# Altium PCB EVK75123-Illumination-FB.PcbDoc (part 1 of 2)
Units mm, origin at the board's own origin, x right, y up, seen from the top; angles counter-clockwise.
Board outline 80 x 50 mm, 4 copper layers (Top Layer, GND, VCC, Bottom Layer), stack 0.99 mm thick; 109 components, 50 nets, 287 pads, 1161 vias.
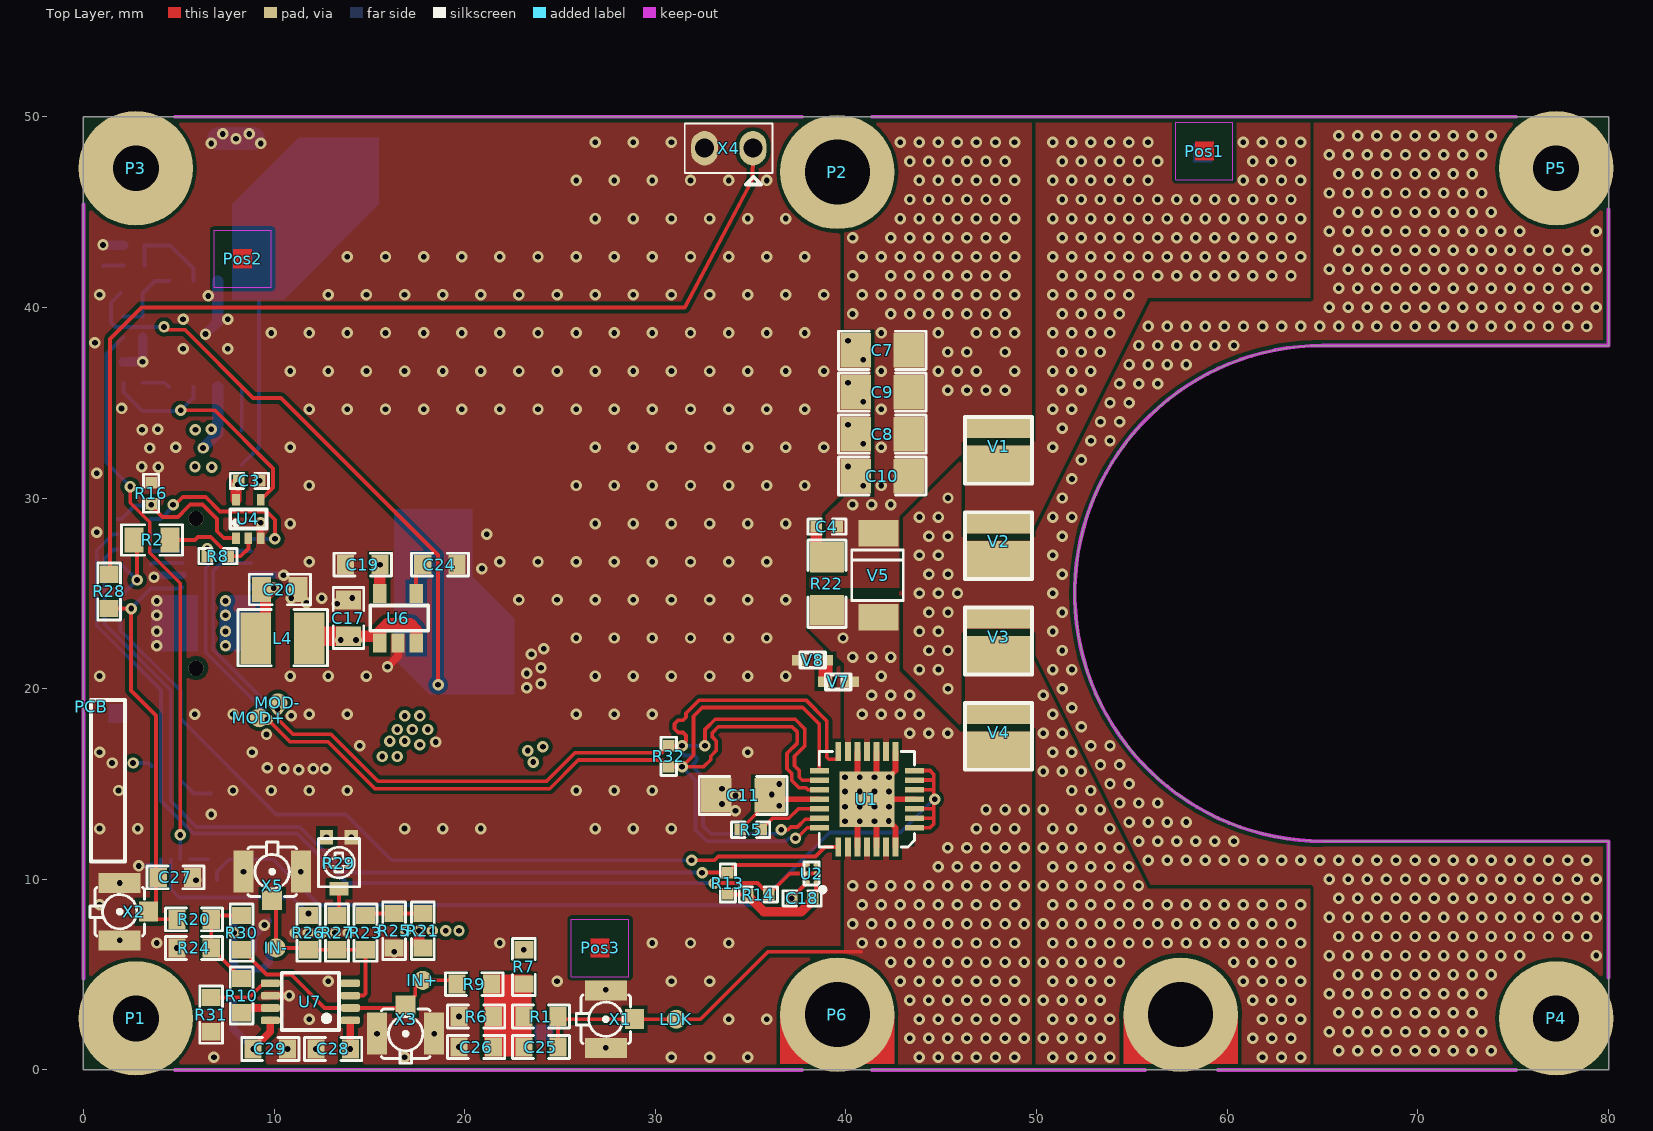
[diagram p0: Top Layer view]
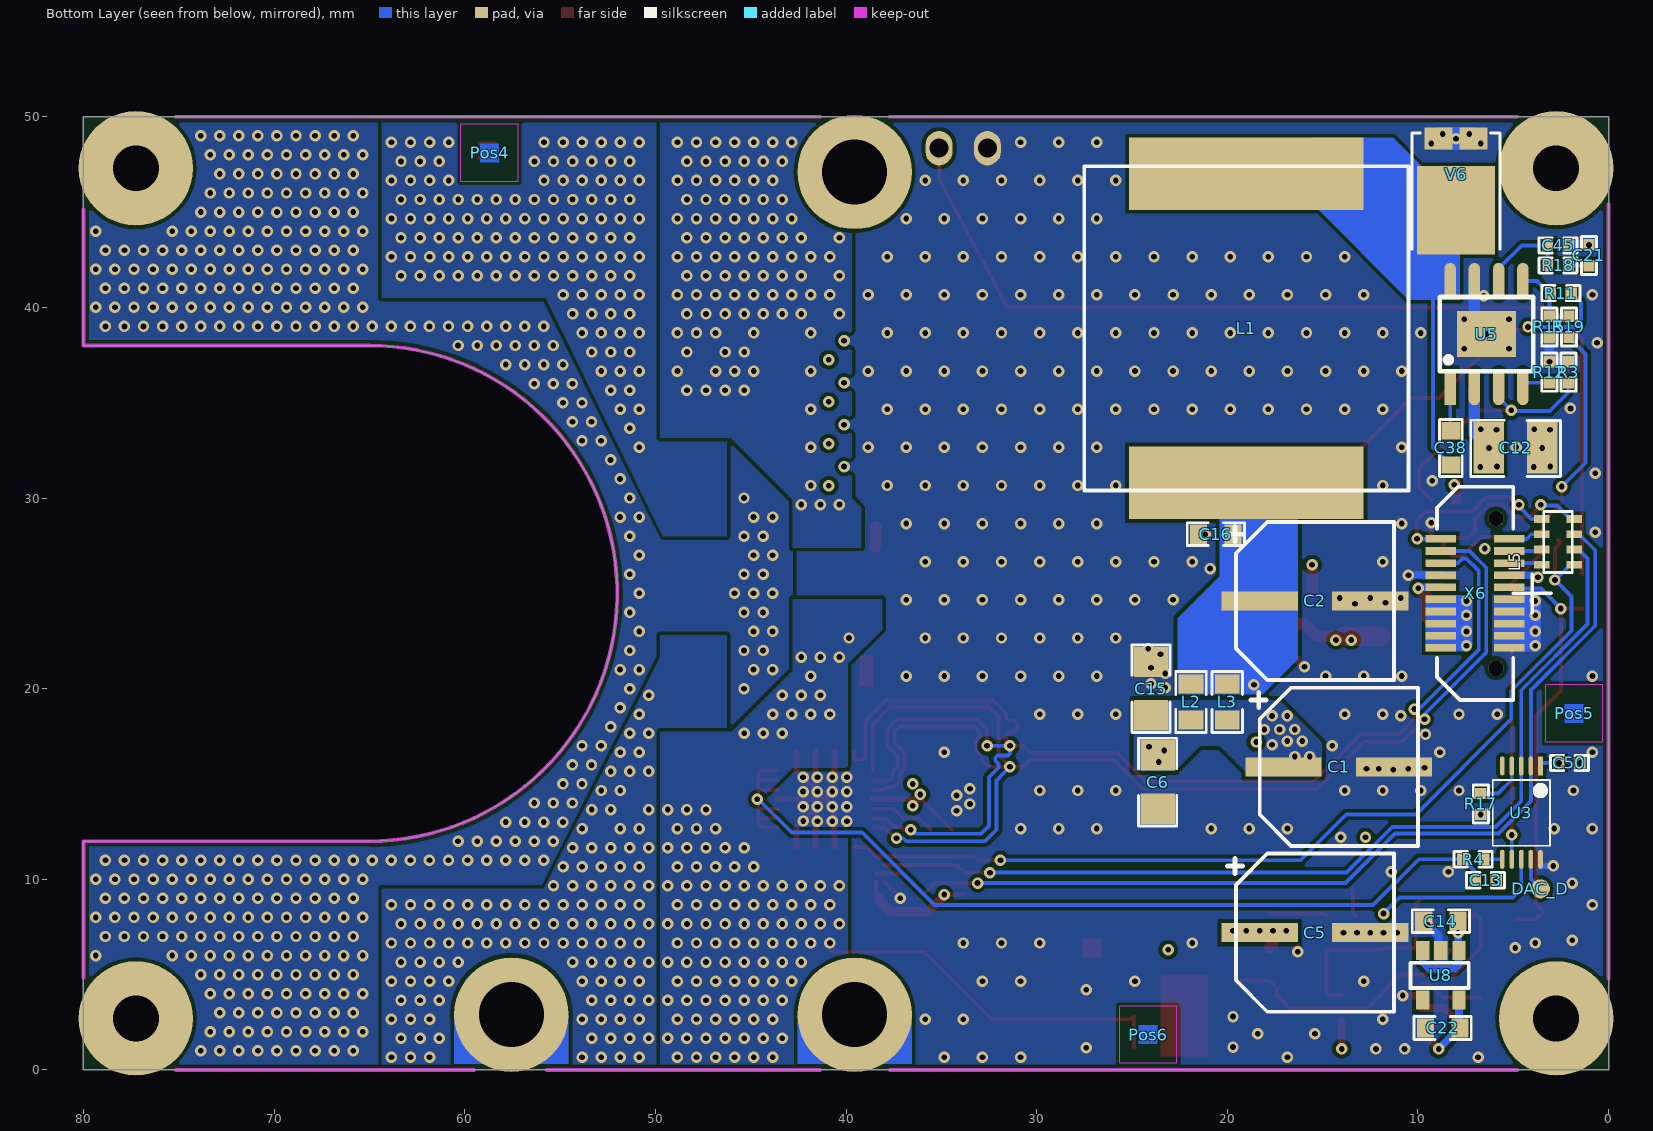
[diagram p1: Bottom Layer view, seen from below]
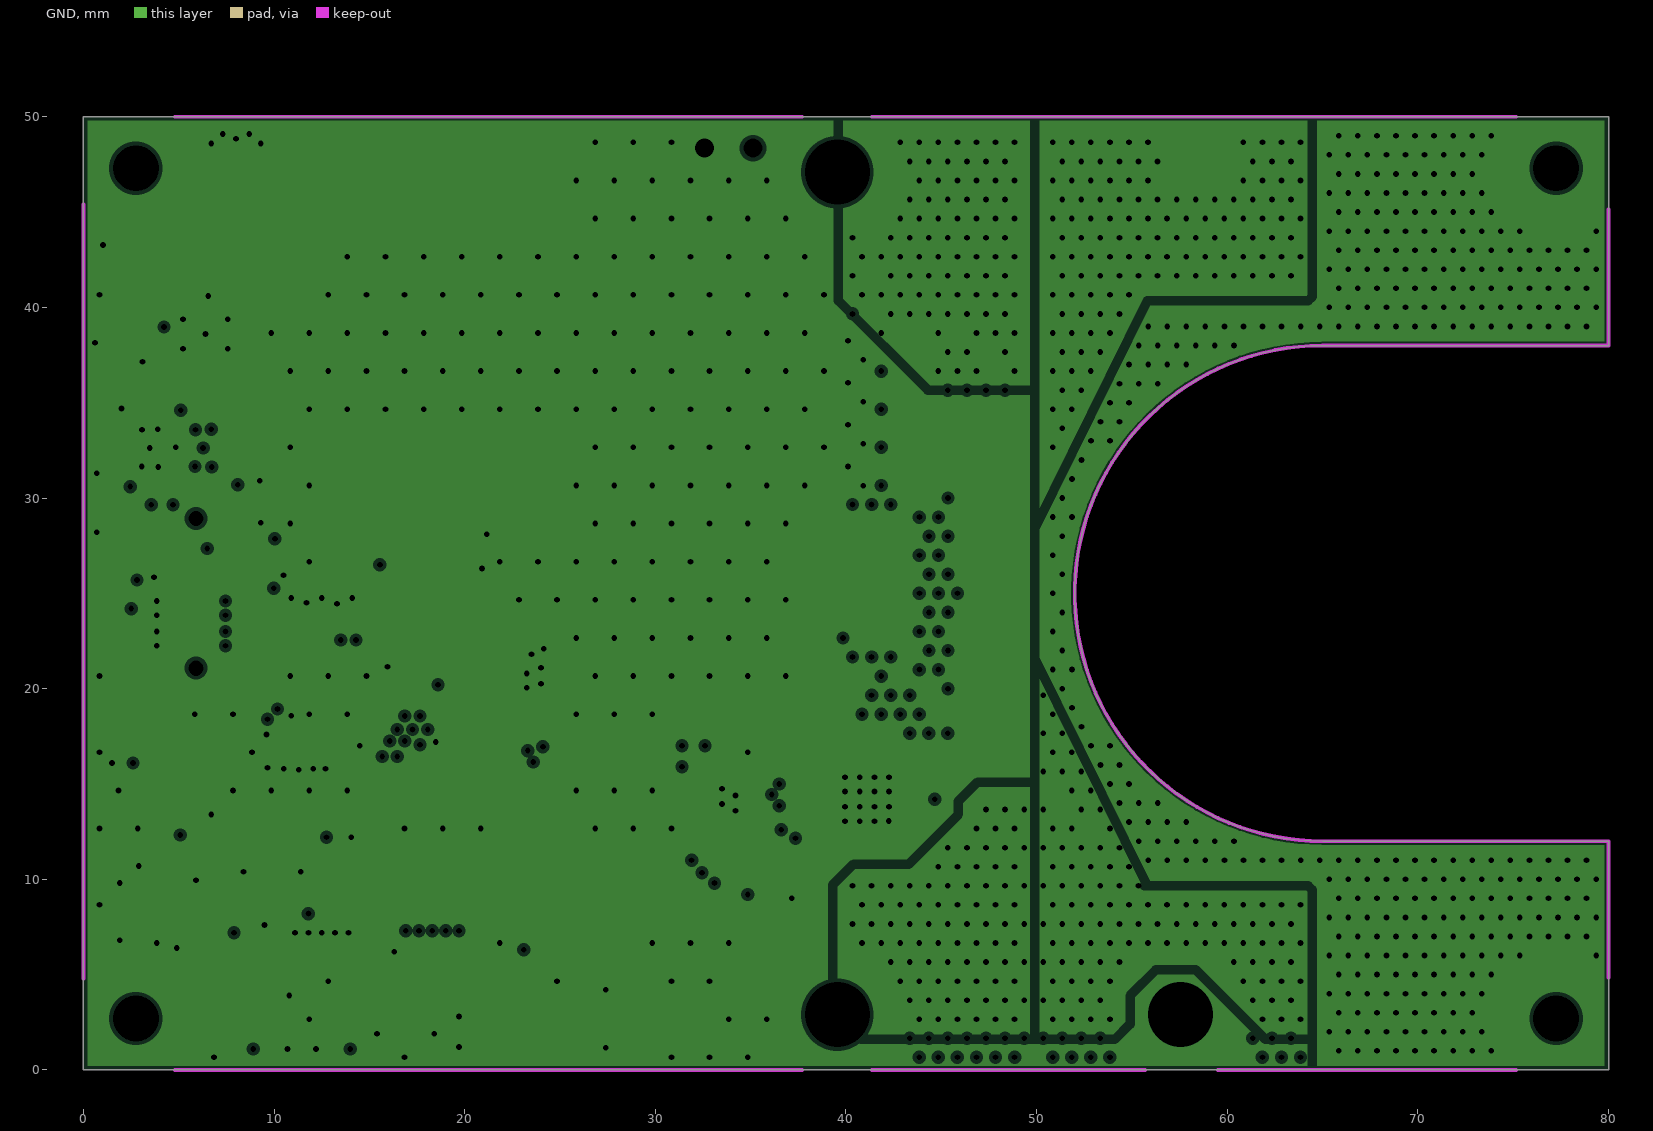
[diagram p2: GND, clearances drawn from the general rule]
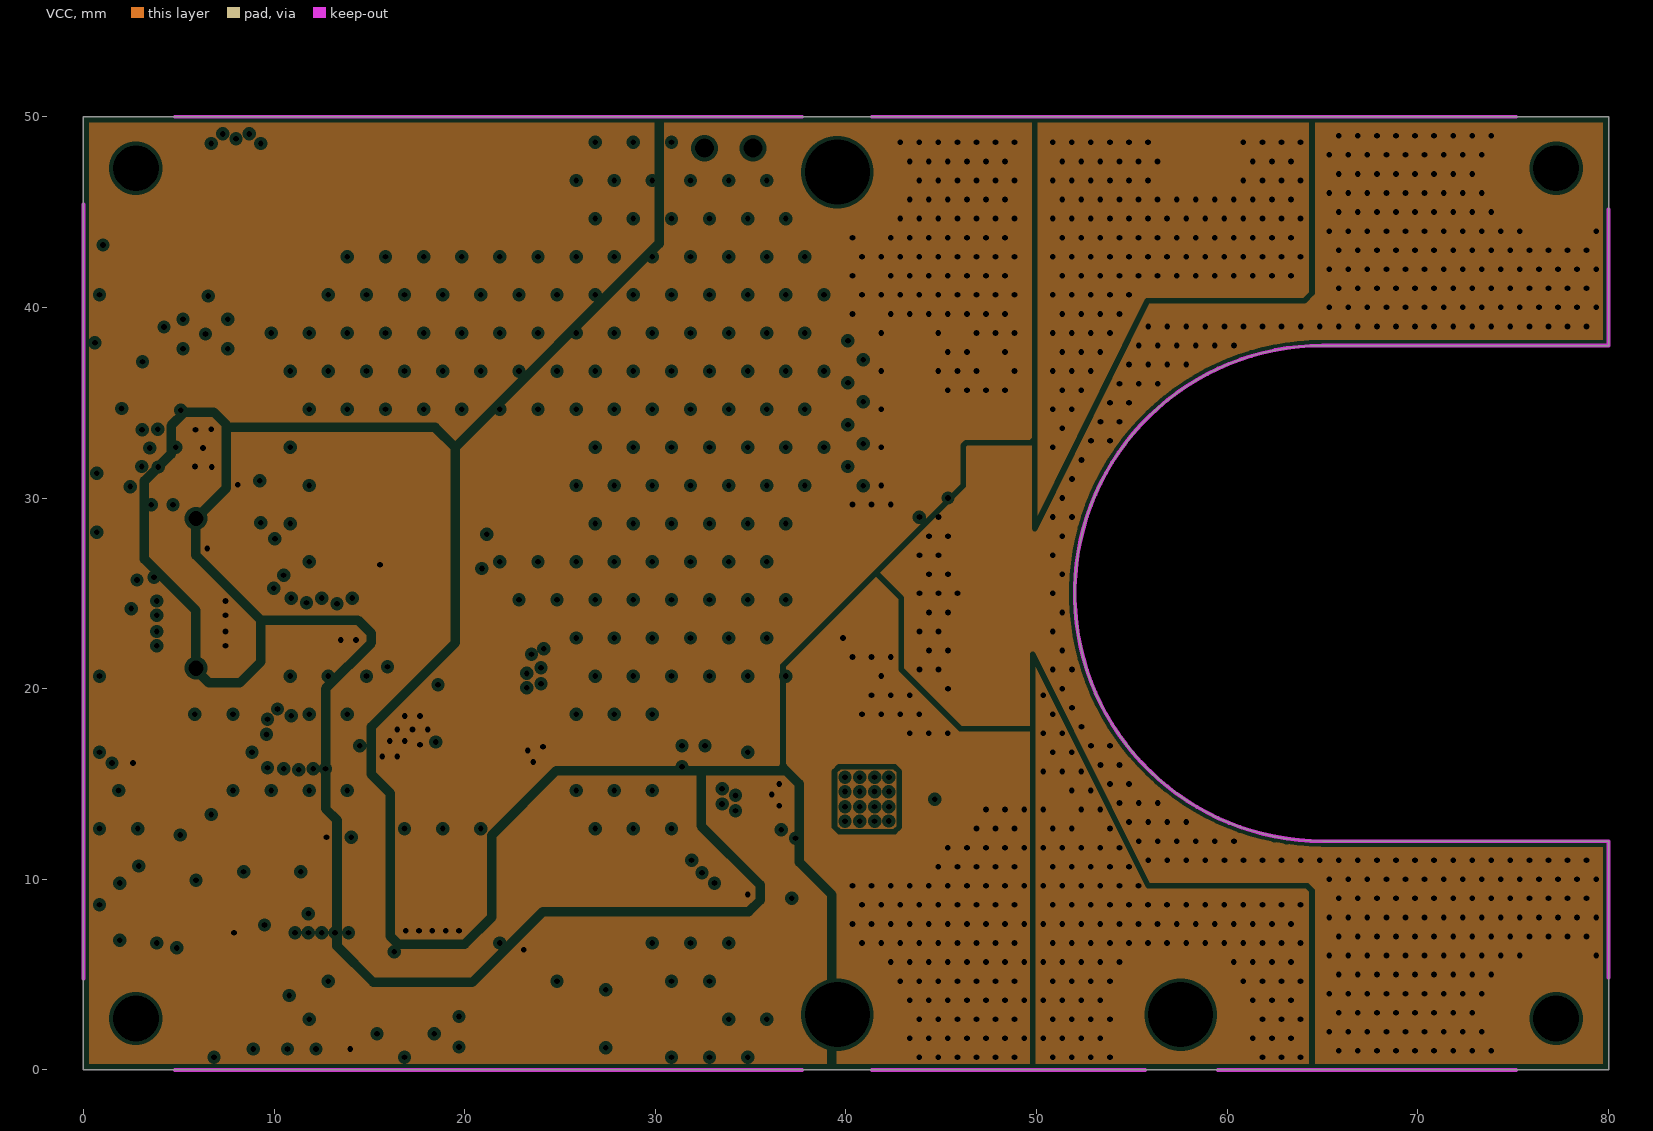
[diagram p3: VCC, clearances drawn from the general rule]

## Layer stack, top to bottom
Top Solder: solder mask 0.025, Solder Resist, Dk 3.5
Top Layer: signal copper 0.07
Dielectric1: prepreg 0.15, FR-4, Dk 4.3
GND: plane copper 0.07, net (Multiple Nets)
Dielectric3: core 0.41, FR-4, Dk 4.47
VCC: plane copper 0.07, net (Multiple Nets)
Dielectric2: prepreg 0.15, FR-4, Dk 4.3
Bottom Layer: signal copper 0.07
Bottom Solder: solder mask 0.025, Solder Resist, Dk 3.5

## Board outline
0,0 0,50 80,50 80,38 65,38 ccw(c65,25) 65,12 80,12 80,0

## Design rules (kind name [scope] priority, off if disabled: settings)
AssemblyTestPointUsage [not (NetPinCount = 1)] p1: allowmultiple=TRUE
AssemblyTestpoint AssemblyTestpoint_Pad [(IsPad And (OnTopLayer)OR (OnBottom))] p1: testpointundercomponent=TRUE minsize=0.8 maxsize=3 preferedsize=0.8 minholesize=0 maxholesize=0 preferedholesize=0 testpointgrid=0.025 usegrid=FALSE gridtolerance=0 allowsidebottom=TRUE minspacing=2.54
AssemblyTestpoint AssemblyTestpoint_Via [(IsVia)] p2: testpointundercomponent=TRUE minsize=0.6 maxsize=0.8 preferedsize=0.8 minholesize=0 maxholesize=0.3 preferedholesize=0.3 testpointgrid=0.025 usegrid=FALSE gridtolerance=0 allowsidebottom=TRUE minspacing=2.54
AssemblyTestpoint AssemblyTestpoint_THT [(IsPad And OnMultiLayer)] p3: testpointundercomponent=TRUE minsize=0.5 maxsize=5 preferedsize=1.524 minholesize=0 maxholesize=3 preferedholesize=0.813 testpointgrid=0.025 usegrid=FALSE gridtolerance=0 allowsidetop=TRUE allowsidebottom=TRUE
AssemblyTestpoint [All] p4: testpointundercomponent=TRUE minsize=1.016 maxsize=2.54 preferedsize=1.524 minholesize=0 maxholesize=1.016 preferedholesize=0.813 testpointgrid=0.025 usegrid=TRUE gridtolerance=0 allowsidetop=TRUE allowsidebottom=TRUE
Clearance Clearance_Hole [All vs not PadIsPlated] p1: gap=0.23 ignorepadtopadclearanceinfootprint=FALSE except(0: Arc-Hole Track-Hole SMDPad-Hole THPad-Hole Via-Hole Fill-Hole Poly-Hole Region-Hole Text-Hole)
Clearance Clearance_poly [inpolygon] p2: gap=0.2 ignorepadtopadclearanceinfootprint=FALSE except(0: Arc-Hole Track-Hole SMDPad-Hole THPad-Hole Via-Hole Fill-Hole Poly-Hole Region-Hole Text-Hole)
Clearance [All] p3: gap=0.15 ignorepadtopadclearanceinfootprint=FALSE
ComponentClearance [not HasFootprint('PAD_1mm_SMD')] p1: gap=0.1 collisioncheckmode=3 verticalgap=0.1 showdistances=FALSE
DiffPairsRouting [InDifferentialPair('MOD')] p1: maxlimit=0.2 minlimit=0.2 mostfreqgap=0.2 toplayer_minwidth=0.192 toplayer_maxwidth=0.192 toplayer_prefwidth=0.192 bottomlayer_minwidth=0.192 bottomlayer_maxwidth=0.192 bottomlayer_prefwidth=0.192 maxuncoupledlength=17
HoleSize [All] p1: absolutevalues=TRUE maxlimit=3.5 minlimit=0.3 maxpercent=80.000 minpercent=20.000
MatchedLengths MOD [InxSignalClass('MOD')] p1: tolerance=0.2 checknetsindiffpair=FALSE checkdiffpairvsdiffpair=TRUE checkxsignals=TRUE checkothers=TRUE
MatchedLengths MOD_DC [InxSignalClass('All xSignals')] p2: tolerance=0.2 checknetsindiffpair=TRUE checkdiffpairvsdiffpair=FALSE checkxsignals=FALSE checkothers=FALSE
MinimumSolderMaskSliver [All vs IsVia] p1: minsoldermaskwidth=0.1
PlaneClearance PlaneClearance_MH [InPadClass('MH')] p1: clearance=0.5
PlaneClearance [All] p2: clearance=0.2
PlaneConnect [All] p1: planeconnectstyle=Direct reliefexpansion=0.5 reliefentries=4 reliefconductorwidth=0.3 reliefairgap=0.2
PolygonConnect [All] p1: connectstyle=Direct reliefconductorwidth=0.3 reliefentries=4 polygonreliefangle="90 Angle" airgapwidth=0.254
RoutingVias [All] p1: holewidth=0.3 width=0.6 viastyle="Through Hole" minholewidth=0.3 minwidth=0.6 maxholewidth=0.3 maxwidth=0.6
SilkToSolderMaskClearance SilkscreenOverComponentPads [IsPad] p1: minsilkscreentomaskgap=0.254 clearancetoexposedcopper=TRUE
SolderMaskExpansion SolderMaskExpansion_Via [IsVia] p1: expansion=-0.05
SolderMaskExpansion SolderMaskExpansion_ALL [All] p2: expansion=0.05
UnConnectedPin [All] p1:
ViasUnderSMD [All] p1: allowed=TRUE
Width [All] p1: maxlimit=3 minlimit=0.2 preferedwidth=0.2 checkconnectedcopper=TRUE
21 further rules are at their usual default settings.

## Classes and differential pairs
pad class MH: Free-H1 P1-1 P2-1 P3-1 P4-1 P5-1 P6-1
component class U_Laserdriver: C4 C7 C8 C9 C10 C11 C13 C25 C26 C27 C28 C29 IN+ IN- LDK R1 R4 R5 R6 R7 R9 R10 R20 R21 R22 R23 R24 R25 R26 R27 R28 R29 R30 R31 R32 U1 U7 V1 V2 V3 V4 V5 V7 V8 X1 X2 X3 X4 X5
net class <HiSpeed>: CMPO LDK MOD_N MOD_P NAMS2 NAMS3 NAMS4 NAMS5 NAMS6 NAMS7 NAMS8 NAMS9 NAMS10 NetC25_2 NetIN+_1 NetR10_1
net class <Power>: 1V8 3V3 5V0 17V 24V GND VLD
component class EVK75123-Illumination-FB: C3 C17 C18 C20 C50 DAC_D L4 L5 MOD+ MOD- PCB R2 R8 R13 R14 R16 R17 U2 U3 U4 X6
net class DIFF100: MOD_N MOD_P
component class U_Power: 24V C1 C2 C5 C6 C12 C14 C15 C16 C19 C21 C22 C24 C38 C45 L1 L2 L3 P1 P2 P3 P4 P5 P6 Pos1 Pos2 Pos3 Pos4 Pos5 Pos6 R3 R11 R12 R15 R18 R19 U5 U6 U8 V6
differential pair MOD: +MOD_P -MOD_N

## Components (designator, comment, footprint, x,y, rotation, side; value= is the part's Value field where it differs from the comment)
C1 "Polarized Capicator" ELKO_SMD-8x7 14.15,15.9 r0 bottom
C2 "Polarized Capicator" ELKO_SMD-8x7 15.4,24.6 r0 bottom
C3 "Capacitor non-polarized" 0402 8.7,30.9 r0 top
C4 "Capacitor non-polarized" 0402 39,28.5 r0 top
C5 "Polarized Capicator" ELKO_SMD-8x7 15.4,7.2 r0 bottom
C6 "Capacitor non-polarized" 1206 23.65,15.1 r270 bottom
C7 "Capacitor non-polarized" 1206 41.9,37.75 r0 top
C8 "Capacitor non-polarized" 1206 41.9,33.35 r0 top
C9 "Capacitor non-polarized" 1206 41.9,35.55 r0 top
C10 "Capacitor non-polarized" 1206 41.9,31.15 r0 top
C11 "Capacitor non-polarized" 1206 34.6,14.4 r0 top
C12 "Capacitor non-polarized" 1210 4.875,32.625 r0 bottom
C13 "Capacitor non-polarized" 0402 6.45,9.95 r0 bottom
C14 "Capacitor non-polarized" 0603 8.793,7.8 r180 bottom
C15 "Capacitor non-polarized" 1206 24,20 r270 bottom
C16 "Capacitor non-polarized" 0603 20.6,28.1 r0 bottom
C17 "Capacitor non-polarized" 0805 13.9,23.7 r270 top
C18 "Capacitor non-polarized" 0402 37.7,9 r0 top
C19 "Capacitor non-polarized" 0603 14.65,26.5 r0 top
C20 "Capacitor non-polarized" 0805 10.3,25.2 r180 top
C21 "Capacitor non-polarized" 0402 1.025,42.725 r270 bottom
C22 "Capacitor non-polarized" 0603 8.7,2.2 r180 bottom
C24 "Capacitor non-polarized" 0603 18.7,26.5 r0 top
C25 "Capacitor non-polarized" 0603 24,1.2 r180 top
C26 "Capacitor non-polarized" 0603 20.6,1.2 r180 top
C27 "Capacitor non-polarized" 0603 4.825,10.1 r0 top
C28 "Capacitor non-polarized" 0603 13.1,1.1 r180 top
C29 "Capacitor non-polarized" 0603 9.8,1.1 r0 top
C38 "Capacitor non-polarized" 0603 8.275,32.625 r90 bottom
C45 "Capacitor non-polarized" 0402 2.65,43.25 r0 bottom
C50 "Capacitor non-polarized" 0402 2.05,16.1 r0 bottom
DAC_D "Test Pad" PAD_1mm_SMD 3.575,9.5 r180 bottom
IN+ "Test Pad" PAD_1mm_SMD 17.8,4.7 r0 top
IN- "Test Pad" PAD_1mm_SMD 10.1,6.4 r0 top
L1 "Inductor" VIS-IHLP-6767DZ 19,38.9 r270 bottom
L2 "Ferrite" 0805 21.9,19.3 r270 bottom
L3 "Ferrite" 0805 20,19.3 r270 bottom
L4 "Inductor" 1210 10.45,22.65 r0 top
L5 "Ferrite" 1206_FB-array 2.65,27.7 r90 bottom
LDK "Test Pad" PAD_1mm_SMD 31.1,2.659 r0 top
MOD+ "Test Pad" PAD_1mm_SMD 9.225,18.475 r0 top
MOD- "Test Pad" PAD_1mm_SMD 10.2,19.25 r0 top
P1 "Test Pad" PAD_M2-5x5#1 2.75,2.7 r270 top
P2 "Test Pad" PAD_M2-5x5#2 39.55,47.1 r270 top
P3 "Test Pad" PAD_M2-5x5#1 2.75,47.3 r270 top
P4 "Test Pad" PAD_M2-5x5#1 77.25,2.7 r270 top
P5 "Test Pad" PAD_M2-5x5#1 77.25,47.3 r270 top
P6 "Test Pad" PAD_M2-5x5#2 39.55,2.9 r90 top
PCB "850-5390" PCB 0.725,19.05 r270 top
Pos1 "Position" Pos-QUADRAT 58.8,48.2 r0 top
Pos2 "Position" Pos-QUADRAT 8.35,42.55 r0 top
Pos3 "Position" Pos-QUADRAT 27.1,6.4 r0 top
Pos4 "Position" Pos-QUADRAT 58.7,48.1 r180 bottom
Pos5 "Position" Pos-QUADRAT 1.8,18.7 r180 bottom
Pos6 "Position" Pos-QUADRAT 24.15,1.85 r180 bottom
R1 "Resistor" 0603 24,2.8 r180 top
R2 "Resistor" 0805 3.6,27.8 r0 top
R3 "Resistor" 0402 2.1,36.6 r270 bottom
R4 "Resistor" 0402 7.1,11.05 r180 bottom
R5 "Resistor" 0402 35,12.6 r180 top
R6 "Resistor" 0603 20.6,2.8 r180 top
R7 "Resistor" 0603 23.1,5.4 r270 top
R8 "Resistor" 0402 7.05,26.95 r180 top
R9 "Resistor" 0603 20.5,4.5 r180 top
R10 "Resistor" 0603 8.3,3.9 r90 top
R11 "Resistor" 0402 2.5,40.75 r0 bottom
R12 "Resistor" 0402 3.1,36.6 r90 bottom
R13 "Resistor" 0402 33.8,9.8 r270 top
R14 "Resistor" 0402 35.4,9.2 r180 top
R15 "Resistor" 0402 3.1,38.975 r90 bottom
R16 "Resistor" 0402 3.55,30.25 r90 top
R17 "Resistor" 0402 6.7,13.95 r90 bottom
R18 "Resistor" 0402 2.65,42.2 r180 bottom
R19 "Resistor" 0402 2.075,38.975 r270 bottom
R20 "Resistor" 0603 5.8,7.9 r180 top
R21 "Resistor" 0603 17.8,7.3 r90 top
R22 "Resistor" 1206 39,25.5 r90 top
R23 "Resistor" 0603 14.8,7.2 r270 top
R24 "Resistor" 0603 5.8,6.4 r180 top
R25 "Resistor" 0603 16.3,7.3 r270 top
R26 "Resistor" 0603 11.8,7.2 r270 top
R27 "Resistor" 0603 13.3,7.2 r270 top
R28 "Resistor" 0603 1.35,25.1 r270 top
R29 "Trimmer" POZ2AN 13.4,10.878 r180 top
R30 "Resistor" 0603 8.3,7.2 r90 top
R31 "Resistor" 0603 6.7,2.9 r90 top
R32 "Resistor" 0402 30.7,16.45 r270 top
U1 "iC-HG" QFN28-0.5-5-0.9 41.1,14.2 r180 top
U2 "TMP108" BGA6-0.4-0.25-1.2x0.8 38.2,10.3 r180 top
U3 "MCP4728" MSOP10-0.5-5 4.575,13.5 r270 bottom
U4 "Single-Gate Dual-Input AND-Logic-Gate" SOT353-0.65--2.6 8.65,28.9 r90 top
U5 "TPS54061" PSO8-1.27-7.3 6.4,38.6 r90 bottom
U6 "LP2985" SOT23-5-0.95--3.6 16.5,23.7 r90 top
U7 "LTC6752HMS8-2" TSSOP8-0.65--5 11.9,3.575 r180 top
U8 "High-Speed LDO Voltage-Regulator" SOT23-5-0.95--3.6 8.793,4.958 r270 bottom
V1 "Light Emitting Diode" PCW-SMT-2 48,32.5 r0 top
V2 "Light Emitting Diode" PCW-SMT-2 48,27.5 r0 top
V3 "Light Emitting Diode" PCW-SMT-2 48,22.5 r0 top
V4 "Light Emitting Diode" PCW-SMT-2 48,17.5 r0 top
V5 "Schottky Diode" SOD128 41.7,26.5 r270 top
V6 "Default Diode" TO-277-3 8,46.1 r0 bottom
V7 "Z-Diode" SOD523 39.6,20.35 r180 top
V8 "Z-Diode" SOD523 38.25,21.5 r180 top
X1 "Amphenol SMA-connector right-angled" HIR-2-U.FL-U.FL-R-SMT 27.4,2.659 r0 top
X2 "Amphenol SMA-connector right-angled" HIR-2-U.FL-U.FL-R-SMT 1.9,8.3 r0 top
X3 "Amphenol SMA-connector right-angled" HIR-2-U.FL-U.FL-R-SMT 16.9,1.9 r90 top
X4 "CON2(1)" PADS-2-2.54 33.85,48.35 r180 top
X5 "Amphenol SMA-connector right-angled" HIR-2-U.FL-U.FL-R-SMT 9.9,10.4 r270 top
X6 "CON20(1-2)" SAM-LSS-110-02-F-DV-A 7,25 r270 bottom locked

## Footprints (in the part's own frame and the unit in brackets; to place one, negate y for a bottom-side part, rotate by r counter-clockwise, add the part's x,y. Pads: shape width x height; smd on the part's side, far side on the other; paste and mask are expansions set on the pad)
0402 [mm]
  rect 0.6x0.6 smd: 1(-0.55,0) 2(0.55,0)
  silkscreen extent -1,-0.4 1,0.4, body extent -0.51,-0.25 0.51,0.25, height 0.41
0603 [mm]
  rect 0.9x1 smd: 1(-0.9,0) 2(0.9,0)
  silkscreen extent -1.5,-0.6 1.5,0.6, body extent -0.89,-0.38 0.89,0.38, height 0.76
0805 [mm]
  rect 1x1.3 smd: 1(-0.95,0) 2(0.95,0)
  silkscreen extent -1.6,-0.8 1.6,0.8, body extent -1,-0.51 1,0.51, height 1
1206 [mm]
  rect 1.6x1.8 smd: 1(-1.4,0) 2(1.4,0)
  silkscreen extent -2.3,-1 2.3,1, body extent -1.45,-0.76 1.45,0.76, height 1.51
1206_FB-array [mm]
  rect 0.4x0.8 smd: 1(-1.2,-0.85) 2(-0.4,-0.85) 3(0.4,-0.85) 4(1.2,-0.85) 5(1.2,0.85) 6(0.4,0.85) 7(-0.4,0.85) 8(-1.2,0.85)
  silkscreen extent -1.6,-0.75 1.6,0.75, body extent -1.6,-0.76 1.6,0.76, height 0.8
1210 [mm]
  rect 1.6x2.7 smd: 1(-1.4,0) 2(1.4,0)
  silkscreen extent -2.35,-1.45 2.35,1.5, body extent -1.61,-1.26 1.61,1.3, height 2.51
BGA6-0.4-0.25-1.2x0.8 [mm]
  round 0.25 smd: A1(-0.225,0.45) A2(0.225,0.45) B1(-0.225,0) B2(0.225,0) C1(-0.225,-0.45) C2(0.225,-0.45)
  silkscreen extent -0.69,-0.6 0.4,0.96, body extent -0.4,-0.6 0.4,0.6, height 0.63
ELKO_SMD-8x7 [mm] "Elko"
  rect 4x1 smd: 1(2.9,0) 2(-2.9,0)
  silkscreen extent -4.15,-4.15 4.6,4.15, body extent -4.5,-4.15 4.5,4.15, height 6.9
HIR-2-U.FL-U.FL-R-SMT [mm]
  rect 2.2x1.05 smd: 1(0,1.5) 3(0,-1.5)
  rect 1x1.05 smd: 2(1.5,0)
  silkscreen extent -1.55,-1.27 1.3,1.27, body extent -1.55,-1.5 1.55,1.5, height 1.25
MSOP10-0.5-5 [mm]
  rect 1x0.25 smd: 1(-2.45,1)
  oval 1x0.25 smd: 2(-2.45,0.5) 3(-2.45,0) 4(-2.45,-0.5) 5(-2.45,-1) 6(2.45,-1) 7(2.45,-0.5) 8(2.45,0) 9(2.45,0.5) 10(2.45,1)
  silkscreen extent -1.7,-1.5 1.74,1.5, body extent -2.58,-1.5 2.58,1.5, height 1.11
PAD_1mm_SMD [mm]
  round 1 smd paste-1: 1(0,0)
PAD_M2-5x5#1 [mm]
  round 6 hole 2.4 paste-1.5: 1(0,0)
PAD_M2-5x5#2 [mm]
  round 6 hole 3.4 paste-1.5: 1(0,0)
PADS-2-2.54 [mm]
  oval 1.4x1.8 hole 1: 1(-1.27,0) 2(1.27,0)
  silkscreen extent -2.29,-1.3 2.31,1.9, body extent -2.54,-1.27 2.54,1.27, height 9.25
PCB [mm]
  rect 0.2x0.2 on Top Overlay mask+0.05: 1(0,-0.325)
  silkscreen extent -0.35,-0.33 8.13,1.45
PCW-SMT-2 [mm]
  rect 3.5x1.1 smd mask+0.05: 1(0,1.2)
  rect 3.5x2 smd mask+0.05: 2(0,-0.75)
  Top Layer pour cut-out: -1.75,0.65 -1.75,0.25 1.75,0.25 1.75,0.65
  silkscreen extent -1.75,-1.75 1.75,1.75, body extent -1.75,-1.75 1.75,1.75, height 2
Pos-QUADRAT [mm] "Positioning mark cross"
  Top Layer region: -0.5,-0.5 0.5,-0.5 0.5,0.5 -0.5,0.5
  Top Layer keep-out lines w0: -1.5,-1.5 -1.5,1.5 1.5,1.5 1.5,-1.5 -1.5,-1.5
POZ2AN [mm]
  rect 0.7x0.75 smd: 1(-0.65,-1.327) 3(0.65,-1.327)
  rect 1x0.7 smd: 2(0,1.378)
  silkscreen extent -1.08,-1.26 1.07,1.27, body extent -1.05,-1.17 1.05,1.53, height 0.8
PSO8-1.27-7.3 [mm]
  rect 2.41x3.1 smd paste-3 mask-3: 0(0,0)
  rect 1.9x0.6 smd: 1(-2.78,1.905)
  oval 1.9x0.6 smd: 2(-2.78,0.635) 3(-2.78,-0.635) 4(-2.78,-1.905) 5(2.78,-1.905) 6(2.78,-0.635) 7(2.78,0.635) 8(2.78,1.905)
  silkscreen extent -1.95,-2.45 1.95,2.45, body extent -1.95,-2.45 1.95,2.45, height 1.7
QFN28-0.5-5-0.9 [mm]
  rect 2.9x2.9 smd paste-2: 0(0,0)
  rect 1x0.3 smd paste-0.025: 1(-2.5,1.5) 2(-2.5,1) 3(-2.5,0.5) 4(-2.5,0) 5(-2.5,-0.5) 6(-2.5,-1) 7(-2.5,-1.5) 15(2.5,-1.5) 16(2.5,-1) 17(2.5,-0.5) 18(2.5,0) 19(2.5,0.5) 20(2.5,1) 21(2.5,1.5)
  rect 0.3x1 smd paste-0.025: 8(-1.5,-2.5) 9(-1,-2.5) 10(-0.5,-2.5) 11(0,-2.5) 12(0.5,-2.5) 13(1,-2.5) 14(1.5,-2.5) 22(1.5,2.5) 23(1,2.5) 24(0.5,2.5) 25(0,2.5) 26(-0.5,2.5) 27(-1,2.5) 28(-1.5,2.5)
  silkscreen extent -2.5,-2.5 2.5,2.5, body extent -2.5,-2.5 2.5,2.5, height 0.91
SAM-LSS-110-02-F-DV-A [mm] "SAM-LSS-105-01-F-DV-A"
  rect 0.4x1.6 smd: 1(2.857,-1.8) 2(2.858,1.8) 3(2.222,-1.8) 4(2.223,1.8) 5(1.587,-1.8) 6(1.588,1.8) 7(0.952,-1.8) 8(0.953,1.8) 9(0.317,-1.8) 10(0.318,1.8) 11(-0.318,-1.8) 12(-0.317,1.8) 13(-0.953,-1.8) 14(-0.952,1.8) 15(-1.588,-1.8) 16(-1.587,1.8) 17(-2.223,-1.8) 18(-2.222,1.8) 19(-2.858,-1.8) 20(-2.857,1.8)
  round 0.8 hole 0.8 unplated: A1(3.925,1.1) A2(-3.925,1.1)
  silkscreen extent -5.59,-2 5.59,2, body extent -5.57,-2.3 5.53,2.3, height 7.45
SOD128 [mm]
  rect 1.4x2.1 smd: 1(2.75,0) 2(-1.65,0)
  silkscreen extent -0.77,-1.4 1.88,1.3, body extent -2.07,-1.4 3.18,1.3, height 1.11
SOD523 [mm]
  rect 0.75x0.55 smd: 1(0.7,0) 2(-0.7,0)
  silkscreen extent -0.65,-0.4 0.65,0.4, body extent -0.8,-0.4 0.8,0.4, height 0.6
SOT23-5-0.95--3.6 [mm]
  rect 1x0.7 smd: 1(-1.3,0.95) 2(-1.3,0) 3(-1.3,-0.95) 4(1.3,-0.95) 5(1.3,0.95)
  silkscreen extent -0.67,-1.59 0.66,1.46, body extent -1.45,-1.45 1.35,1.45, height 1.09
SOT353-0.65--2.6 [mm]
  rect 0.6x0.4 smd: 1(-1,0.65) 2(-1,0) 3(-1,-0.65) 4(1,-0.65) 5(1,0.65)
  silkscreen extent -0.5,-0.95 0.5,0.95, body extent -1.1,-0.95 1.1,0.95, height 0.95
TO-277-3 [mm] "TO-277-3 / PowerDI"
  rect 1.45x1.15 smd: 1(-0.92,-2.75) 3(0.92,-2.75)
  rect 4.1x4.65 smd: 2(0,1)
  silkscreen extent -2.3,-3.05 2.3,3.05, body extent -2.03,-3.3 2.02,3.3, height 1.17
TSSOP8-0.65--5 [mm]
  rrect50% 1x0.4 smd: 1(-2.1,0.975) 2(-2.1,0.325) 3(-2.1,-0.325) 4(-2.1,-0.975) 5(2.1,-0.975) 6(2.1,-0.325) 7(2.1,0.325) 8(2.1,0.975)
  silkscreen extent -1.5,-1.53 1.5,1.47, body extent -2.6,-1.53 2.6,1.47, height 1.21
VIS-IHLP-6767DZ [mm] "Speicherdrossel"
  rect 3.8x12.3 smd: 1(-8.1,0) 2(8.1,0)
  silkscreen extent -8.5,-8.5 8.5,8.5, body extent -8.61,-8.58 8.56,8.6, height 3.91

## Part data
C1 C2 C5: library part 44276342-0de9-47a7-a7a6-11334c4a2d95, "C-39u-35V-20%-30mR", Manufacturer=Panasonic, Supplier Part Number 1=2354808, Toleranz=20%
C3 C13 C18 C50: library part 54C877D5-E705-4C14-AD3D-8F4F7B57D597, "C-0402-100n-16V-10%", Manufacturer=Murata, Supplier Part Number 1=08506103, Toleranz=10%
C4: library part 0097ADC0-227E-4059-A51E-B4508658C31A, "C-0402-270p-50V-5%", Manufacturer=KEMET, Supplier Part Number 1=1414585, Toleranz=5%
C6 C7 C8 C9 C10 C11 C15: library part 6574bd8d-1f7f-4017-8c13-fc1ff6c564f2, "C-1206-100n-50V-5%", Manufacturer=TDK, Supplier Part Number 1=810-CGA5L2C0G1H104J, Toleranz=5%
C12: library part c11633e3-883f-4ea1-bab5-305a930c1712, "C-1210-2u2-100V-X7R", Manufacturer=Kemet, Supplier Part Number 1=1793832, Toleranz=10%
C14 C19 C22: library part 62C539F0-6F12-4C64-8973-B77ABBA35E0D, "C-0603-1u-25V-10%", Manufacturer=Kemet, Supplier Part Number 1=1288202, Toleranz=10%
C16 C24 C25 C26 C27 C28 C29 C38: library part F4F417EB-80BB-43BD-9294-E69FEC10CC02, "C-0603-100n-50V-10%", Manufacturer=MULTICOMP, Supplier Part Number 1=1759122, Toleranz=10%
C17 C20: library part 47BE2105-E645-4B7D-88B5-189FA600BE5F, "C-0805-10u-10V-10%", Manufacturer=PhyComp, Supplier Part Number 1=9402136, Toleranz=10%
C21: library part 0D03DA8E-6E9D-48FA-B2D5-DDC88D2A4CF2, "C-0402-18n-16V-10%", Manufacturer=AVX, Supplier Part Number 1=478-1117-1-ND, Toleranz=10%
C45: library part 11FE33DF-B8B2-497C-ADE2-798944BCF4BE, "C-0402-15p-50V-5%", Manufacturer=PhyComp, Supplier Part Number 1=3019172, Toleranz=5%
DAC_D IN+ IN- LDK MOD+ MOD-: library part D58E77CC-74E0-4972-9B60-0D1F1EE06ED8, "Test Pad 1mm", Manufacturer=Bluetechnix, Supplier Part Number 1=-----
L1: library part c927bdf3-e195-4335-ae34-2dcccbc64859, "L-VIS-IHLP-6767-22u-6.2A-20%", Manufacturer=Vishay, Supplier Part Number 1=1853811, Toleranz=20%
L2 L3: library part 4558f3ef-a2ca-4732-a97e-33e36c5aad12, "F-0805-120Z-5A", Frequenz=300MHz, Manufacturer="MEC MARCOM", Supplier Part Number 1=1308778
L4: library part 5A39A3C7-8FFF-4AB6-80A4-55595FBEE935, "L-1210-10u-450mA", Manufacturer=Murata, Supplier Part Number 1=9522204, Toleranz=10%
L5: library part 17bc767e-4081-41c9-96a1-8705f6a55660, "F-1206array-600Z-100mA", Frequenz=220MHz, Manufacturer="Taiyo Yuden", Supplier Part Number 1=587-2692-1-ND
P1 P2 P3 P4 P5 P6: library part d95d2f47-965b-47b2-ac00-e8d5b9325de3, "M2 Mounting Hole 5x5", Manufacturer=Bluetechnix
PCB: library part 5ec15bad-9016-406e-8801-bfda4c5ae292, "PCB_EVK75123-Illumination-FB V1.0", Manufacturer=Bluetechnix
Pos1 Pos2 Pos3 Pos4 Pos5 Pos6: library part A97550DC-E5EA-465D-9168-34E3565B8720, "Pos-QUADRAT-3mm", Manufacturer=Bluetechnix, Supplier Part Number 1=-
R1 R6 R7 R21 R24 R25 R30: library part AA0CF608-2A67-4058-8450-88B6A96542D7, "R-0603-10k-1%", Manufacturer=Multicomp, Supplier Part Number 1=9330399, Toleranz=1%
R2: library part 96878DCE-2E24-48BD-A958-A9B2669E8EA5, "R-0805-0R-5%", Manufacturer=YAGEO, Supplier Part Number 1=1117368, Toleranz=5%
R3 R15 R18: library part A4A7BB00-465D-4C1E-8319-4836672F5686, "R-0402-18k-1%", Manufacturer=YAGEO, Supplier Part Number 1=9239383, Toleranz=1%
R4 R32: library part 5753A1E5-EBD2-4BBF-8026-C9AE8047C4EC, "R-0402-100R-1%", Manufacturer=YAGEO, Toleranz=1%
R5 R8 R13 R14 R16 R17: library part 87ff11f6-a19c-4fd3-a86d-d729e9959c04, "R-0402-3k6-1%", Manufacturer=MULTICOMP, Supplier Part Number 1=1358057, Toleranz=1%
R9 R10 R20 R23 R26 R27 R28: library part E495C68F-9C71-4733-8E6B-D3B3727AEEA9, "R-0603-0R", Manufacturer=Multicomp, Supplier Part Number 1=9331662
R11 R12: library part 0499915E-9BF4-4C7F-8B08-D182950F3B89, "R-0402-330k-1%", Manufacturer=YAGEO, Supplier Part Number 1=9239537, Toleranz=1%
R19: library part 57b0607b-283e-4831-8b97-1b038861c010, "R-0402-130k-1%", Manufacturer=Multcomp, Supplier Part Number 1=2072607, Toleranz=1%
R22: library part 1a6a65a5-8098-42a8-a07d-6c7b13c9a3e6, "R-1206-1R-1%-0.5W", Manufacturer=Multicomp, Supplier Part Number 1=1576602, Toleranz=1%
R29: library part 1DD80AC4-4383-45C6-B1FE-58D03BB158C7, "R-Trimmer-SMD-10k-30%", Manufacturer=Murata, Supplier Part Number 1=1771725, Toleranz=30%
R31: library part 35F436D8-BE29-4562-B269-D4190D404CCA, "R-0603-56k-1%", Manufacturer=Multicomp, Supplier Part Number 1=9331360, Toleranz=1%
U1: library part 900fa9a9-c7df-41b9-b82b-983ec3f9771c, "3 A LASER SWITCH", Manufacturer=iC-Haus
U2: library part 1756c951-2cf8-4c64-a988-e546f59afa21, "±1°C Accurate 12bit Digital Temperature Sensor", Manufacturer="Texas Instruments", Supplier Part Number 1=2496408
U3: library part 7021478d-2d84-431d-b8be-32d6dfcf2c4d, "12-Bit Digital-to-Analog Converter with EEPROM Memory", Manufacturer=Microchip, Supplier Part Number 1=579-MCP4728-E/UN
U4: library part B349E2D1-8349-4508-822A-E73FFBEB3634, "74AHC1G08", Manufacturer="Texas Instruments", Supplier Part Number 1=1470829
U5: library part 83e8cd34-1e26-4937-9357-3a852f02699a, "4.5 V to 60 V Input, 5 A, Step Down DC-DC Converter with Eco-mode", Frequenz="100kHz : 2.5MHz", Manufacturer="Texas Instruments", Supplier Part Number 1=595-TPS54560DDAR
U6: library part 595174d6-4f0f-4a85-858e-941119242838, "3.3V, Micropower 100 mA Low-Noise Ultra Low-Dropout Regulator", Manufacturer="Microchip Technology", Supplier Part Number 1=TC1015-3.3VCT713CT-ND
U7: library part c98d9747-e96e-4882-9a1f-65f891a5ac5f, "280MHz, 2.9ns Comparator Rail-to-Rail", Manufacturer="Analog Devices"
U8: library part 70773BAF-7633-4D88-81D5-082B1EC5F3A9, "XC6204B-1V8", Manufacturer=Torex, Supplier Part Number 1=3605802
V1 V2 V3 V4: library part 85e564f8-3a71-4d92-9828-a8b6dfe11ab7, "VCSEL Array Laser Diode", Farbtemp.=-, Manufacturer="Princeton Optronics"
V5: library part 39a5ee8a-d88f-425e-8062-ede2c4d3764b, "PMEG3050EP", Manufacturer=NXP, Supplier Part Number 1=1829197
V6: library part a2494603-b754-4332-b2d6-676b3f1482f6, "12A, 100V Ultra-Low Vf Schottky Rectifier", Manufacturer=Fairchild, Supplier Part Number 1=512-FSV12100V
V7 V8: library part CC9D59A8-5C7A-4322-9DFB-934945E300CD, "PESD5V0S1UB - 5.0V", Manufacturer=NXP, Supplier Part Number 1=8737711
X1 X2 X3 X5: library part C2DB380A-A97D-4691-B92E-D6F0F144D3C9, "HIR-2-U.FL-U.FL-R-SMT", Manufacturer=Hirose, Supplier Part Number 1=3908021
X4: library part E2448B04-DC6E-4F04-8FE3-EBFE442A9048, "CON2(1)[Stiftleiste][Jumper]", Manufacturer="Tyco Electronics", Supplier Part Number 1=3417645
X6: library part 379f8e5c-a288-4eeb-8f71-ca0e0501eadd, "High speed hermaphrodotoc strip", Manufacturer=Samtec, Supplier Part Number 1=LSS-110-02-F-DV-A

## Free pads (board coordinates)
  round 6 hole 3.4: H1(57.55,2.9)

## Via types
v1: diameter 0.6, hole 0.3, Top Layer to Bottom Layer, tented both sides, 1159 vias
v2: diameter 0.6, hole 0.3, Top Layer to Bottom Layer, 2 vias

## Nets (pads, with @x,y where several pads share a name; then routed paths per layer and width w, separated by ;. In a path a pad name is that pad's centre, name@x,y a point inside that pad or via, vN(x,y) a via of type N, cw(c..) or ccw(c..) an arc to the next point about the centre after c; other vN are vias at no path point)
1V8: C22.2 C29.1 U7.8 U8.5 | length 4.9
  Top Layer w0.4: v1(8.9,1.1) 9.8,2 U7.8@9.8,2.6
  Bottom Layer w0.4: U8.5@7.843,3.658 7.843,2.157 v1(8.9,1.1)
3V3: C3.1 C18.2 C19.2 R8.2 R13.2 R14.2 U2.A1 U4.5 U6.5 | length 8.5
  Top Layer w0.2: R13.2@33.8,9.25 33.85,9.2 v1(34.85,9.2) ; C18.2@38.25,9 38.425,9.175 U2.A1@38.425,9.85
  Top Layer w0.5: v1(34.85,9.2) 34.85,9.134 35.684,8.3 37.66,8.3 38.25,8.89 C18.2@38.25,9
  Top Layer w0.6: U4.5@8,29.9 C3.1@8,30.75 ; U6.5@15.55,25 v1(15.55,26.5)
  other v1: 6.5,27.35 8.1,30.7
5V0: C11.2 C14.2 C17.2 C28.1 C50.2 L4.2 R5.2 R7.1 R29.3 U1.18 U3.1 U6.1 U6.3 U7.1 U8.1 U8.3 | length 19
  Top Layer w0.2: R5.2@34.45,12.6 C11.2@36.1,14.25
  Top Layer w0.3: C11.2@36.1,14.2 U1.18@38.6,14.2
  Top Layer w0.4: v1(7.893,7.2) v1@7.9,7.207 ; v1(14,1.1) U7.1@14,2.6
  Top Layer w0.6: C17.2@13.9,22.75 15.3,22.75 15.65,23.1 15.65,23.107 15.943,23.4 17.15,23.4 17.45,23.1 U6.3@17.45,22.4
  Top Layer w1: L4.2@11.95,22.75 C17.2@13.9,22.75
  Bottom Layer w0.2: v1(2.6,16.1) 3.425,16.1 U3.1@3.575,15.95
  Bottom Layer w0.4: C14.2@7.893,7.8 v1(7.893,7.2) 7.893,6.308 U8.1@7.843,6.258 7.843,5.557 8.1,5.3 9.4,5.3 9.743,5.643 U8.3@9.743,6.258
  other v1: 23.1,6.3 12.75,12.205 36.5,13.85 36.1,14.45 36.5,15 13.5,22.55 14.3,22.55
17V: C2.1 C16.1 L1.2 L2.1 L3.1 R11.1 | length 30.8
  Top Layer w0.2: v2(4.225,38.975) 4.375,38.825 5.325,38.825 8.9,35.25 10.354,35.25 18.6,27.004 v1(18.6,20.2)
  Bottom Layer w0.2: R11.1@1.95,40.75 1.44,40.24 1.44,39.206 1.671,38.975 v2(4.225,38.975)
24V: C12.2 U5.2 X6.1 X6.3 X6.5 X6.7 X6.9 | length 3.5
  Bottom Layer w0.6: v1(6.275,32.625) 7.035,33.385 U5.2@7.035,35.82
  other v1: 7.45,22.25 7.45,23 7.45,23.85 7.45,24.6 6.725,31.625 5.85,31.65 5.875,33.575 6.7,33.6
CMPO: R10.2 R20.1 R24.1 R30.2 | length 5.4
  Top Layer w0.2: R10.2@8.3,4.8 R24.1@6.7,6.4 R20.1@6.7,7.9 6.9,8.1 R30.2@8.3,8.1
FB: C27.1 R20.2 R28.2 X2.2 X6.12 | length 22.6
  Top Layer w0.2: R28.2@1.35,24.2 v1(2.5,24.2) 2.5,19.9 3.8,18.6 3.8,8.7 X2.2@3.4,8.3 3.8,7.9 R20.2@4.9,7.9
  Bottom Layer w0.2: v1(2.5,24.2) 3.55,25.25 5.133,25.25 X6.12@5.2,25.318
FB17V: R11.2 R15.2 R19.1 U5.5 | length 3.9
  Bottom Layer w0.2: R19.1@2.075,39.525 R15.2@3.1,39.525 3.1,40.725 3.125,40.75 3.755,41.38 U5.5@4.495,41.38
FBx: R28.1 X4.1 | length 52.3
  Top Layer w0.2: R28.1@1.35,26 1.393,26.043 1.393,38.343 3.05,40 31.543,40 35.094,46.71 35.114,47.953 35.315,48.148 X4.1@35.317,48.15
GND: C1.2 C2.2 C3.2 C5.2 C6.2 C7.1 C8.1 C9.1 C10.1 C11.1 C12.1 C13.1 C14.1 C15.1 C16.2 C17.1 C18.1 C19.1 C20.1 C21.1 C22.1 C24.2 C26.2 C27.2 C28.2 C29.2 C45.1 C50.1 pad.H1 R3.1 R6.2 R12.2 R15.1 R16.2 R17.1 R24.2 R25.2 R29.1 R31.1 U1.0 U1.4 U1.8 U1.10 U1.12 U1.24 U1.26 U1.28 U2.A2 U3.10 U4.3 U5.0 U5.7 U6.2 U7.6 U8.2 V6.1 V6.3 V8.1 X1.1 X1.3 X2.1 X2.3 X3.1 X3.3 X4.2 X5.1 X5.3 X6.2 X6.4 X6.6 X6.8 X6.10 X6.13 X6.14 | length 37
  Top Layer w0.2: v1(37.15,9) 37.15,9.025 U2.A2@37.975,9.85
  Top Layer w0.3: U4.3@9.3,27.9 v1(9.3,28.7) ; U1.24@40.6,11.7 40.6,13.7 U1.0@41.1,14.2 ; U1.12@40.6,16.7 40.6,14.7 U1.0@41.1,14.2 ; U1.26@41.6,11.7 U1.0@41.6,13.7 ; U1.10@41.6,16.7 U1.0@41.6,14.7 ; U1.28@42.6,11.7 42.6,12.7 v1(42.243,13.057) U1.0@41.6,13.7 ; U1.8@42.6,16.7 42.6,15.7 U1.0@41.6,14.7 ; U1.4@43.6,14.2 U1.0@41.1,14.2 ; U1.0@41.1,14.2 U1.0@41.6,14.7 ; U1.0@41.1,14.2 U1.0@41.6,13.7
  Top Layer w0.4: U7.6@9.8,3.9 v1(10.8,3.9) ; v1(15.95,21.15) 16.5,21.7 U6.2@16.5,22.4 ; v1(16.3,6.2) R25.2@16.3,6.4 ; X1.1@27.4,4.159 v1(27.4,4.2)
  Bottom Layer w0.3: v1(2.9,10.7) U3.10@3.575,10.7
  Bottom Layer w0.4: v1@3.625,25.775 v1(3.7,25.85) 3.8,25.95 4.203,25.95 4.203,25.953 X6.14@5.2,25.953 ; U8.2@8.793,6.258 8.9,6.365 8.9,7.007 v1(9.493,7.6) C14.1@9.693,7.8 ; X6.13@8.8,25.953 8.815,25.967 10.432,25.967 v1@10.447,25.953
  Bottom Layer w0.5: v1(1.025,43.275) 1.05,43.25 C45.1@2.1,43.25 ; R3.1@2.1,37.15 v1(3.1,37.15) R15.1@3.1,38.425 ; v1(6.4,38.6) U5.0@7.035,39.235
  Bottom Layer w0.6: U5.0@7.035,39.235 U5.7@7.035,41.38
  Bottom Layer w1.2: V6.1@7.08,48.85 v1(8,48.85) V6.3@8.92,48.85
  other v1: 6.843,0.658 16.843,0.658 30.843,0.658 32.843,0.658 34.843,0.658 10.7,1.1 12.2,1.1 27.4,1.159 19.7,1.2 15.4,1.9 18.4,1.9 11.843,2.658 33.843,2.658 35.843,2.658 19.7,2.8 12.843,4.658 24.843,4.658 30.843,4.658 32.843,4.658 4.9,6.4 3.843,6.658 21.843,6.658 29.843,6.658 31.843,6.658 33.843,6.658 1.9,6.8 11.1,7.2 11.8,7.2 12.5,7.2 13.2,7.2 13.9,7.2 0.843,8.658 1.9,9.8 5.9,9.95 8.4,10.4 11.4,10.4 14.05,12.205 0.843,12.658 2.843,12.658 16.843,12.658 18.843,12.658 20.843,12.658 26.843,12.658 28.843,12.658 30.843,12.658 39.95,13.05 40.725,13.05 41.5,13.05 6.7,13.4 34.2,13.6 39.95,13.8 40.725,13.8 41.5,13.8 42.25,13.8 33.5,13.95 34.2,14.4 39.95,14.6 40.725,14.6 41.5,14.6 42.25,14.6 1.843,14.658 7.843,14.658 9.843,14.658 11.843,14.658 13.843,14.658 25.843,14.658 27.843,14.658 29.843,14.658 33.5,14.75 39.95,15.35 40.725,15.35 41.5,15.35 42.25,15.35 11.3,15.75 10.5,15.8 12.05,15.8 12.7,15.8 9.65,15.85 1.5,16.1 0.843,16.658 8.843,16.658 34.843,16.658 14.5,17.002 18.483,17.2 9.6,17.6 10.9,18.575 5.843,18.658 7.843,18.658 11.843,18.658 13.843,18.658 25.843,18.658 27.843,18.658 29.843,18.658 23.25,20.05 24,20.25 0.843,20.658 10.843,20.658 12.843,20.658 14.843,20.658 26.843,20.658 28.843,20.658 30.843,20.658 32.843,20.658 34.843,20.658 36.843,20.658 23.25,20.8 24,21.1 23.5,21.8 24.15,22.1 3.85,22.25 25.843,22.658 27.843,22.658 29.843,22.658 31.843,22.658 33.843,22.658 35.843,22.658 3.85,23 3.85,23.85 13.3,24.45 11.7,24.5 3.85,24.6 22.843,24.658 24.843,24.658 26.843,24.658 28.843,24.658 30.843,24.658 32.843,24.658 34.843,24.658 36.843,24.658 10.9,24.75 12.5,24.75 14.1,24.75 10.497,25.953 20.9,26.3 11.843,26.658 21.843,26.658 23.843,26.658 25.843,26.658 27.843,26.658 29.843,26.658 31.843,26.658 33.843,26.658 35.843,26.658 21.15,28.1 0.7,28.2 10.843,28.658 26.843,28.658 28.843,28.658 30.843,28.658 32.843,28.658 34.843,28.658 36.843,28.658 11.843,30.658 25.843,30.658 27.843,30.658 29.843,30.658 31.843,30.658 33.843,30.658 35.843,30.658 37.843,30.658 40.9,30.65 9.25,30.9 0.7,31.3 3.925,31.625 3.05,31.65 40.1,31.65 3.475,32.625 4.843,32.658 10.843,32.658 26.843,32.658 28.843,32.658 30.843,32.658 32.843,32.658 34.843,32.658 36.843,32.658 38.843,32.658 40.9,32.85 3.075,33.575 3.9,33.6 40.1,33.85 11.843,34.658 13.843,34.658 15.843,34.658 17.843,34.658 19.843,34.658 21.843,34.658 23.843,34.658 25.843,34.658 27.843,34.658 29.843,34.658 31.843,34.658 33.843,34.658 35.843,34.658 37.843,34.658 2,34.699 40.9,35.05 40.1,36.05 10.843,36.658 12.843,36.658 14.843,36.658 16.843,36.658 18.843,36.658 20.843,36.658 22.843,36.658 24.843,36.658 26.843,36.658 28.843,36.658 30.843,36.658 32.843,36.658 34.843,36.658 36.843,36.658 38.843,36.658 40.9,37.25 5.225,37.825 7.575,37.825 0.6,38.15 40.1,38.25 9.843,38.658 11.843,38.658 13.843,38.658 15.843,38.658 17.843,38.658 19.843,38.658 21.843,38.658 23.843,38.658 25.843,38.658 27.843,38.658 29.843,38.658 31.843,38.658 33.843,38.658 35.843,38.658 37.843,38.658 5.225,39.375 7.575,39.375 6.55,40.6 0.843,40.658 12.843,40.658 14.843,40.658 16.843,40.658 18.843,40.658 20.843,40.658 22.843,40.658 24.843,40.658 26.843,40.658 28.843,40.658 30.843,40.658 32.843,40.658 34.843,40.658 36.843,40.658 38.843,40.658 13.843,42.658 15.843,42.658 17.843,42.658 19.843,42.658 21.843,42.658 23.843,42.658 25.843,42.658 27.843,42.658 29.843,42.658 31.843,42.658 33.843,42.658 35.843,42.658 37.843,42.658 26.843,44.658 28.843,44.658 30.843,44.658 32.843,44.658 34.843,44.658 36.843,44.658 25.843,46.658 27.843,46.658 29.843,46.658 31.843,46.658 33.843,46.658 35.843,46.658 6.7,48.6 9.3,48.6 26.843,48.658 28.843,48.658 30.843,48.658 7.3,49.1 8.7,49.1
I2C.SCL: L5.3 R14.1 U2.B1 U2.B2 U3.2 | length 52.8
  Top Layer w0.2: v1(33.1,9.8) 35.35,9.8 R14.1@35.95,9.2 37.05,10.3 U2.B2@37.975,10.3 U2.B1@38.425,10.3
  Bottom Layer w0.2: L5.3@1.8,28.1 1.542,28.1 0.7,27.257 0.7,23.3 4.075,19.925 U3.2@4.075,15.95 4.075,14.103 5.778,12.4 11.2,12.4 13.8,9.8 22.1,9.8 v1(33.1,9.8)
I2C.SDA: L5.2 R13.1 U2.C2 U3.3 | length 50.2
  Top Layer w0.2: v1(32.45,10.35) R13.1@33.8,10.35 34.2,10.75 U2.C2@37.975,10.75
  Bottom Layer w0.2: L5.2@1.8,27.3 1.576,27.3 1.1,26.824 1.1,23.395 4.575,19.92 U3.3@4.575,15.95 4.575,14.098 5.923,12.75 11.345,12.75 13.745,10.35 v1(32.45,10.35)
LD1: V1.2 V2.1
  other v1: 50.843,32.658 51.343,33.658 50.843,34.658 51.843,34.658 51.343,35.658 52.343,35.658 50.843,36.658 51.843,36.658 52.843,36.658 51.343,37.658 52.343,37.658 53.343,37.658 50.843,38.658 51.843,38.658 52.843,38.658 53.843,38.658 51.343,39.658 52.343,39.658 53.343,39.658 54.343,39.658 50.843,40.658 51.843,40.658 52.843,40.658 53.843,40.658 54.843,40.658 51.343,41.658 52.343,41.658 53.343,41.658 54.343,41.658 55.343,41.658 56.343,41.658 57.343,41.658 58.343,41.658 59.343,41.658 60.343,41.658 61.343,41.658 62.343,41.658 63.343,41.658 50.843,42.658 51.843,42.658 52.843,42.658 53.843,42.658 54.843,42.658 55.843,42.658 56.843,42.658 57.843,42.658 58.843,42.658 59.843,42.658 60.843,42.658 61.843,42.658 62.843,42.658 63.843,42.658 51.343,43.658 52.343,43.658 53.343,43.658 54.343,43.658 55.343,43.658 56.343,43.658 57.343,43.658 58.343,43.658 59.343,43.658 60.343,43.658 61.343,43.658 62.343,43.658 63.343,43.658 50.843,44.658 51.843,44.658 52.843,44.658 53.843,44.658 54.843,44.658 55.843,44.658 56.843,44.658 57.843,44.658 58.843,44.658 59.843,44.658 60.843,44.658 61.843,44.658 62.843,44.658 63.843,44.658 51.343,45.658 52.343,45.658 53.343,45.658 54.343,45.658 55.343,45.658 56.343,45.658 57.343,45.658 58.343,45.658 59.343,45.658 60.343,45.658 61.343,45.658 62.343,45.658 63.343,45.658 50.843,46.658 51.843,46.658 52.843,46.658 53.843,46.658 54.843,46.658 55.843,46.658 60.843,46.658 61.843,46.658 62.843,46.658 63.843,46.658 51.343,47.658 52.343,47.658 53.343,47.658 54.343,47.658 55.343,47.658 56.343,47.658 61.343,47.658 62.343,47.658 63.343,47.658 50.843,48.658 51.843,48.658 52.843,48.658 53.843,48.658 54.843,48.658 55.843,48.658 60.843,48.658 61.843,48.658 62.843,48.658 63.843,48.658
